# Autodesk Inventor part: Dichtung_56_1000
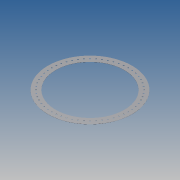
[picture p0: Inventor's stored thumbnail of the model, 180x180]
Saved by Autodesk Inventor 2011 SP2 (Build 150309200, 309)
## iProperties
Created: 2012-06
Part Number: Dichtung_56_1000
Document SubType Name: Modeling
Designer: JRE
Density: 1 g/cm^3
Author: JRE
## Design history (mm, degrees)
sketch "Skizze1"
  geometry: C1 r 550 at (0, 0); C2 r 450 at (0, 0); 1 further point
  constraints: 2 centre point, 2 coincident
  dimensions: "d0" = 1100 diameter of C1; "d1" = 900 diameter of C2
extrude "Extrusion1" new body sketch "Skizze1" distance "d2" = 2; taper "d3" = 0 deg
sketch "Skizze2"
  geometry: C1 r 450 at (0, 0) reference; 1 further point
  constraints: 1 vertical alignment
  dimensions: "d4" = 500 distance of point (0, 500) C1.centre
hole "Hole1" sketch "Skizze2" at (0, 500) diameter "d5" = 17; stored, may be unused: countersink angle "d9" = 90 deg, drill point angle "d11" = 118 deg; dims "d6" = 6, "d7" = 4, "d8" = 2, "d10" = 2
node "Volumenkörper1"
pattern_circular "Runde Anordnung1" dims angle "d13" = 360 deg
